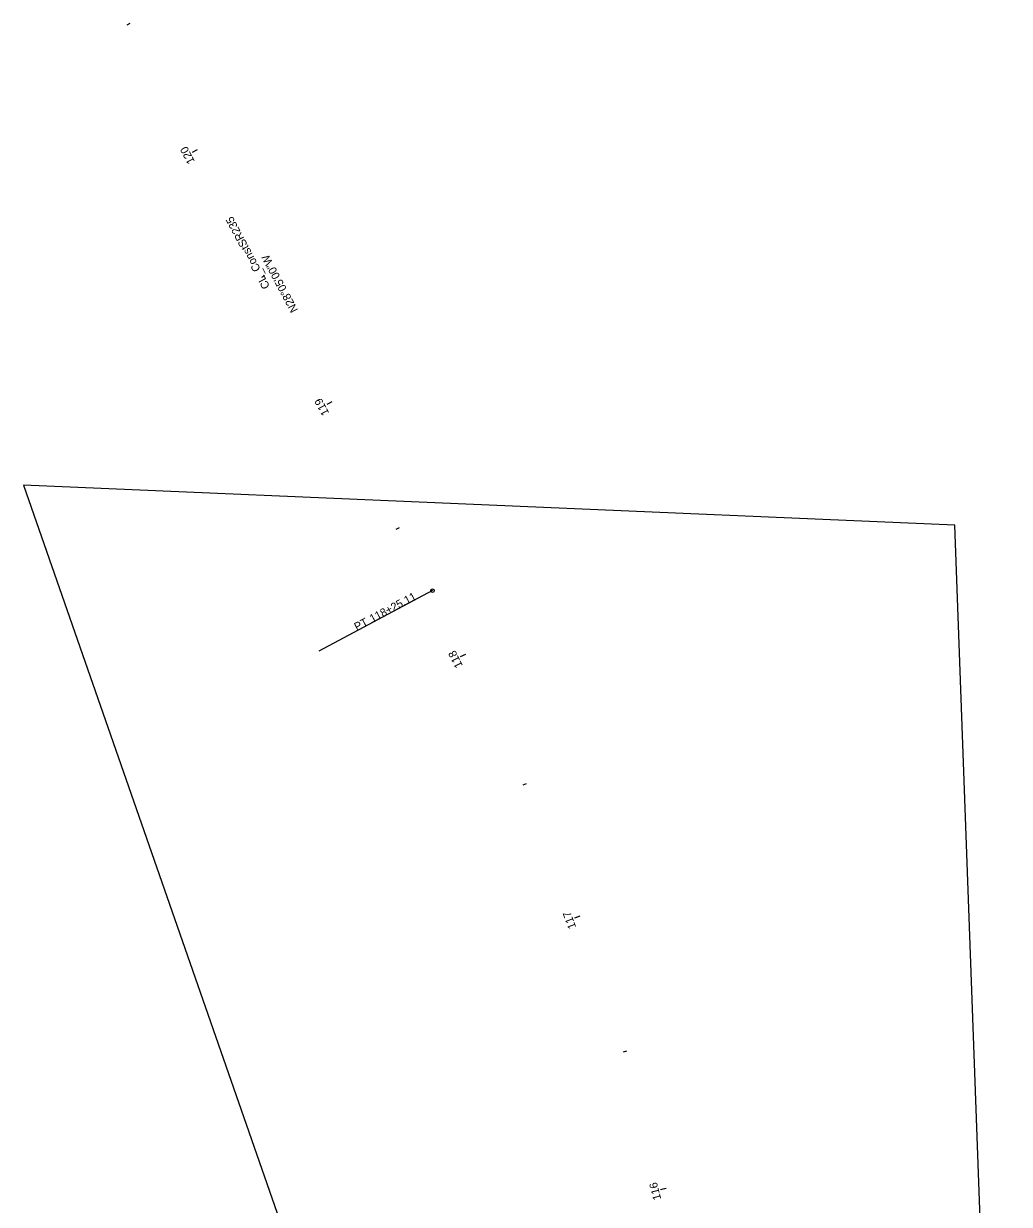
# Model space of a CAD drawing. Extents: x 1564517 to 1565226, y 635740 to 637455.
# Drawn here: x 1564517 to 1564861.8, y 637041.9 to 637455.1 of the extents above; entities that cross this region are included whole.
import ezdxf

# ---------------------------------------------------------------- set-up
doc = ezdxf.new("R2010")
doc.units = 0
for name, color, linetype in [('GE_P_Alignment_1000_Bearings', 7, 'Continuous'), ('GE_P_Alignment_1000_Distances', 7, 'Continuous'), ('GE_P_Alignment_500_Bearings', 7, 'Continuous'), ('GE_P_Alignment_500_Cardinal_Points', 7, 'Continuous'), ('GE_P_Alignment_500_Distances', 7, 'Continuous'), ('UT_P_Water_Cells', 7, 'Continuous'), ('UT_X_Electric', 7, 'Continuous'), ('UT_X_Sanitary_Pressure_Line', 7, 'Continuous'), ('UT_X_Water_Cells', 7, 'Continuous')]:
    doc.layers.add(name, color=color, linetype=linetype)

msp = doc.modelspace()

# ---------------------------------------------------------------- linework, layer by layer
at = {"layer": 'GE_P_Alignment_500_Cardinal_Points'}
msp.add_line((1564660.06, 637256.68), (1564620.35, 637235.5), dxfattribs=at)
msp.add_circle((1564660.06, 637256.68), 0.6, dxfattribs=at)
at = {"layer": 'UT_P_Water_Cells'}
for p, q in [((1564577.72, 637410.98), (1564575.96, 637410.04)), ((1564624.8, 637322.75), (1564623.74, 637322.19)), ((1564671.58, 637234.37), (1564670.51, 637233.84)), ((1564711.56, 637142.76), (1564710.44, 637142.34)), ((1564741.75, 637047.48), (1564740.59, 637047.17))]:
    msp.add_line(p, q, dxfattribs=at)
at = {"layer": 'UT_X_Electric'}
msp.add_lwpolyline([(1564682.06, 636752.05), (1564842.01, 636748.56), (1564861.83, 636755.87), (1564842.73, 637279.63), (1564517.04, 637293.63), (1564662.12, 636876.82)], close=True, dxfattribs=at)
at = {"layer": 'UT_X_Sanitary_Pressure_Line'}
msp.add_line((1564577.72, 637410.98), (1564575.96, 637410.04), dxfattribs=at)
at = {"layer": 'UT_X_Water_Cells'}
for p, q in [((1564554.19, 637455.09), (1564553.13, 637454.53)), ((1564577.72, 637410.98), (1564575.96, 637410.04)), ((1564601.26, 637366.87), (1564600.2, 637366.3)), ((1564624.8, 637322.75), (1564623.04, 637321.81)), ((1564648.34, 637278.64), (1564647.28, 637278.08)), ((1564671.58, 637234.37), (1564669.79, 637233.48)), ((1564692.77, 637189.09), (1564691.67, 637188.61)), ((1564711.56, 637142.76), (1564709.69, 637142.06)), ((1564727.9, 637095.52), (1564726.76, 637095.15)), ((1564741.75, 637047.48), (1564739.81, 637046.97))]:
    msp.add_line(p, q, dxfattribs=at)

# ---------------------------------------------------------------- texts
at = {"layer": 'GE_P_Alignment_1000_Bearings'}
msp.add_text('N28°05\'00"W', height=2.8, rotation=118.0832, dxfattribs=at).set_placement((1564613.09, 637354.9))
at = {"layer": 'GE_P_Alignment_1000_Distances'}
msp.add_text('CL_ConstSR235', height=2.8, rotation=118.0832, dxfattribs=at).set_placement((1564603.27, 637363.11))
at = {"layer": 'GE_P_Alignment_500_Bearings'}
msp.add_text('N28°05\'00"W', height=2.8, rotation=118.0832, dxfattribs=at).set_placement((1564613.09, 637354.9))
at = {"layer": 'GE_P_Alignment_500_Cardinal_Points'}
for s, p in [('118+25.11', (1564638.96, 637245.42)), ('PT', (1564633.59, 637242.56))]:
    msp.add_text(s, height=2.8, rotation=28.0832, dxfattribs=at).set_placement(p)
at = {"layer": 'GE_P_Alignment_500_Distances'}
msp.add_text('CL_ConstSR235', height=2.8, rotation=118.0832, dxfattribs=at).set_placement((1564603.27, 637363.11))
at = {"layer": 'UT_P_Water_Cells'}
msp.add_text('120', height=2.8, rotation=118.0832, dxfattribs=at).set_placement((1564577.02, 637406.89))
at = {"layer": 'UT_X_Sanitary_Pressure_Line'}
msp.add_text('120', height=2.8, rotation=118.0832, dxfattribs=at).set_placement((1564577.02, 637406.89))
at = {"layer": 'UT_X_Water_Cells'}
for s, rotation, p in [('120', 118.0832, (1564577.02, 637406.89)), ('119', 118.0832, (1564624.02, 637318.81)), ('118', 116.5768, (1564670.71, 637230.43)), ('117', 110.577, (1564710.35, 637138.9)), ('116', 104.5772, (1564740.07, 637043.8))]:
    msp.add_text(s, height=2.8, rotation=rotation, dxfattribs=at).set_placement(p)

doc.saveas('drawing.dxf')
